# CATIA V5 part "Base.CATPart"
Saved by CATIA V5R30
Part number: Part1
Bounding box of the stored display mesh (mm): x -50 to 50, y -25 to 25, z 0 to 50
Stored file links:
  D:\PROJECTS\CATIA V56R 2020\Resources\Parts File\c12_catia_v5_6r2020_prt\c12_catia_v5-6r2020 figr_12-15\Base.CATPart
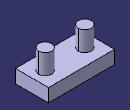
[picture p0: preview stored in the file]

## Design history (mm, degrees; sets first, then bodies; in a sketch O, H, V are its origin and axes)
Body1 (main body)
  Sketch1 on xy-plane, origin (0, 0, 0), H (1, 0, 0), V (0, 1, 0)
    line L1 (50, 25) -> (50, -25)
    line L2 (50, -25) -> (-50, -25)
    line L3 (-50, -25) -> (-50, 25)
    line L4 (-50, 25) -> (50, 25)
    circle A1 centre (-30, 0) radius 10
    point P5 (-30, 0)
    circle A2 centre (30, 0) radius 10
    length L2 = 100
    length L1 = 50
    radius A1 = 10
    distance P5 V = 30
    vertical: L1 V, L3 V
    horizontal: L2 H, L4 H
    equidistance: L1 L3 O, L2 L4 O
    coincidence: P5 H
    symmetry: A1 A2 V
  MultiPad1: profile Sketch1, domains (length 20; length 50; length 50)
